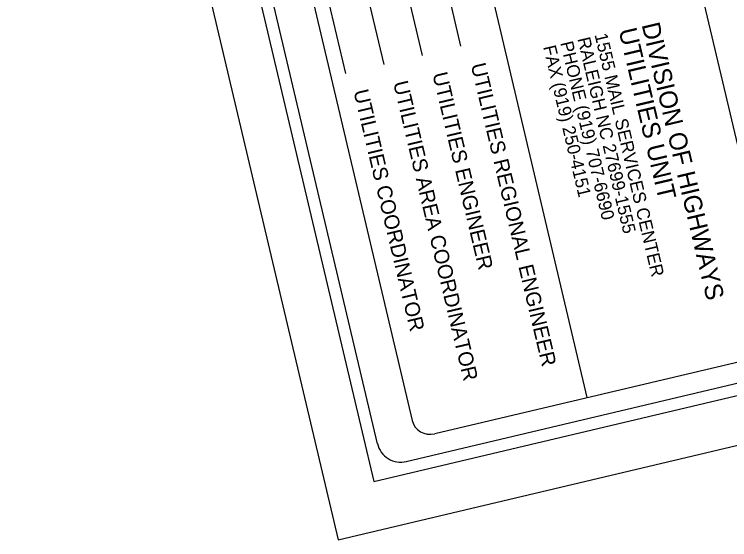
# Model space of a CAD drawing. Extents: x 1439200 to 1642353, y 394562 to 606444.
# Drawn here: x 1440332 to 1441638, y 598050 to 599009 of the extents above; entities that cross this region are included whole.
import ezdxf

# ---------------------------------------------------------------- set-up
doc = ezdxf.new("R2010")
doc.units = 0
doc.layers.add('Level 43', color=7, linetype='Continuous')
doc.layers.add('Water Line Text and Text Box and Leader Line (St)', color=7, linetype='Continuous')

msp = doc.modelspace()

# ---------------------------------------------------------------- linework, layer by layer
at = {"layer": 'Level 43'}
for p, q in [((1441491.5, 599450.7), (1441733.6, 598426.6)), ((1441121, 599397), (1441377.4, 598309.6)), ((1441054.7, 599339.8), (1441146.9, 598950.6)), ((1440984.6, 599323.2), (1441076.8, 598934)), ((1440914.5, 599306.6), (1441006.7, 598917.4)), ((1440816.5, 599289.4), (1441058.1, 598267.6)), ((1440844.4, 599290), (1440936.5, 598900.8)), ((1441099.5, 598243.6), (1441707.5, 598387.5))]:
    msp.add_line(p, q, dxfattribs=at)
msp.add_lwpolyline([(1445632.9, 599164.9), (1443909.8, 606443.8), (1439200, 605328.8), (1440923.1, 598050)], close=True, dxfattribs=at)
for points in [[(1439494.5, 604562.1), (1440994.6, 598225.2)], [(1441047.6, 598192.5), (1445457.7, 599236.5)]]:
    msp.add_lwpolyline(points, dxfattribs=at)
msp.add_arc((1441037.7, 598235.4), 44, 193.3181, 283.3181, dxfattribs=at)
msp.add_ellipse((1441092.2, 598275.3), major_axis=(-33.8, -8), ratio=0.941469, start_param=6.282951, end_param=7.853377, dxfattribs=at)
at = {"layer": 'Water Line Text and Text Box and Leader Line (St)'}
msp.add_lwpolyline([(1439298.8, 605293.4), (1440988.4, 598155.9), (1445527, 599230.3), (1443837.3, 606367.8)], close=True, dxfattribs=at)

# ---------------------------------------------------------------- texts
at = {"layer": 'Level 43'}
for s, height, p in [('UTILITIES UNIT', 32.969, (1441435.3, 598980)), ('DIVISION OF HIGHWAYS', 32.969, (1441477.4, 598990)), ('1555 MAIL SERVICES CENTER', 23.423, (1441391.4, 598971.7)), ('PHONE (919) 707-6690', 23.423, (1441328.8, 598956.9)), ('RALEIGH NC 27699-1555', 23.423, (1441360.1, 598964.3)), ('FAX (919) 250-4151', 23.423, (1441297.5, 598949.5)), ('UTILITIES REGIONAL ENGINEER', 27.199, (1441165.3, 598916.7)), ('UTILITIES ENGINEER', 27.199, (1441095.2, 598900)), ('UTILITIES AREA COORDINATOR', 27.199, (1441023.5, 598884.1)), ('UTILITIES COORDINATOR', 27.199, (1440951, 598868.5))]:
    msp.add_text(s, height=height, rotation=283.3038, dxfattribs=at).set_placement(p)

doc.saveas('drawing.dxf')
